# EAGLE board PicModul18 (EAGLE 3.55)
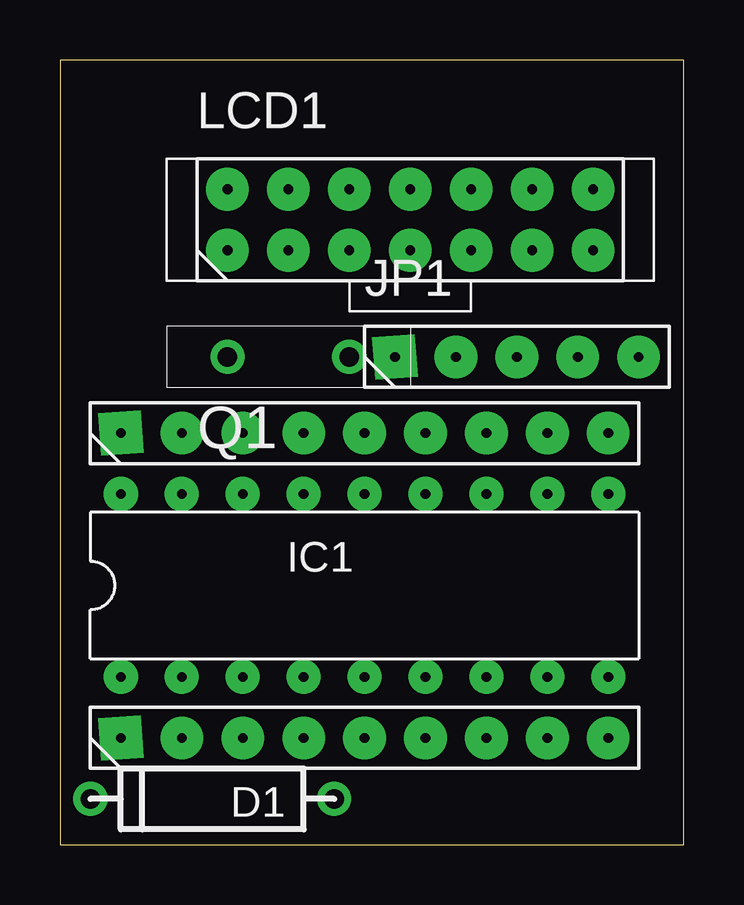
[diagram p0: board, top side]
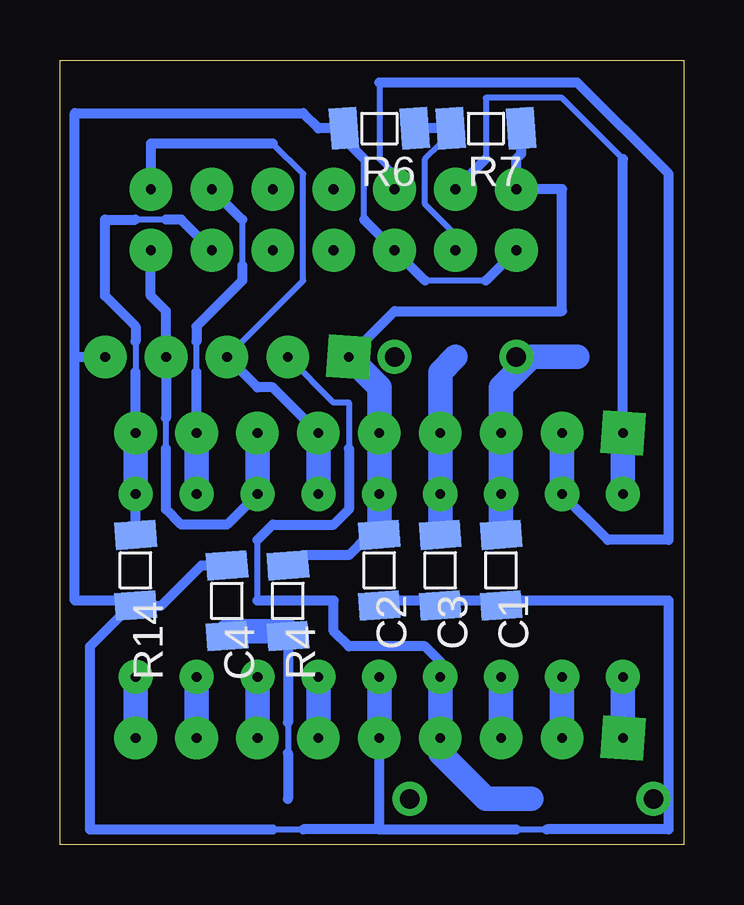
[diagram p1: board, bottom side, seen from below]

Size 26.02 x 32.69 mm. Coordinates in mm from the lower left corner, seen from the top.
Outline: 0,0 26.02,0 26.02,32.69 0,32.69 0,0
Copper layers used: Bottom

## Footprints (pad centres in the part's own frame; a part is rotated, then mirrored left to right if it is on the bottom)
06 = smd 1.143 x 1.702 rotated 4.4:  1.473,0 | smd 1.143 x 1.702 rotated 4.3:  -1.473,0
O04 = drill 0.813 pad 1.422 round:  0,0;  10.16,0
9 = drill 0.406 pad 1.778 square:  0,0 | drill 0.406 pad 1.778 round:  5.08,0;  10.16,0;  12.7,0;  7.62,0;  2.54,0;  15.24,0;  17.78,0;  20.32,0
L-18 = drill 0.406 pad 1.422 round:  -10.16,-3.81;  -7.62,-3.81;  5.08,-3.81;  7.62,-3.81;  -5.08,-3.81;  -2.54,-3.81;  2.54,-3.81;  0,-3.81;  10.16,-3.81;  10.16,3.81;  7.62,3.81;  5.08,3.81;  2.54,3.81;  0,3.81;  -2.54,3.81;  -5.08,3.81;  -7.62,3.81;  -10.16,3.81
5 = drill 0.406 pad 1.778 square:  0,0 | drill 0.406 pad 1.778 round:  5.08,0;  10.16,0;  7.62,0;  2.54,0
7 = drill 0.406 pad 1.778 round:  0,0;  2.54,0;  5.08,0;  7.62,0;  10.16,0;  10.16,2.54;  7.62,2.54;  5.08,2.54;  2.54,2.54;  0,2.54;  12.7,0;  12.7,2.54;  15.24,0;  15.24,2.54
ARZ_ST = drill 0.813 pad 1.422 round:  0,0;  5.08,0

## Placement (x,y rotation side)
C1  27p  [06]  7.62,11.43 90 bottom
C2  100n  [06]  12.7,11.43 90 bottom
C3  27p  [06]  10.16,11.43 90 bottom
C4  100n  [06]  19.05,10.16 90 bottom
D1  BAT41  [O04]  11.43,1.91 180 top
E$1  [9]  2.54,4.45 0 top
E$2  [9]  2.54,17.14 0 top
IC1  16F84P  [L-18]  12.7,10.79 0 top
JP1  PINHD-1X5  [5]  13.97,20.32 0 top
LCD1  LTN211  [7]  6.99,24.77 0 top
Q1  4MHz  [ARZ_ST]  6.99,20.32 0 top
R4  47k  [06]  16.51,10.16 90 bottom
R6  1k  [06]  12.7,29.84 0 bottom
R7  12k  [06]  8.26,29.84 0 bottom
R14  4k7  [06]  22.86,11.43 90 bottom

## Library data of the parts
C1-C4 R4 R6 R7 R14 = mysmd
D1 = holgnorm
E$1 E$2 IC1 LCD1 = holg_plt
JP1 = PINHEAD
Q1 = bts

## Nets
+5V: C2. E$2. IC1. JP1. LCD1. R4. R7.
GND: C1. C2. C3. C4. E$1. IC1. JP1. LCD1. R6. R14.
N$1: C1. E$2. IC1. Q1.
N$3: C3. E$2. IC1. Q1.
N$5: E$2. IC1. LCD1.
N$6: E$2. IC1. LCD1. R14.
N$7: E$2. IC1. JP1. LCD1.
N$8: E$2. IC1. JP1. LCD1.
N$10: C4. D1. R4.
N$12: D1. E$1. IC1. JP1.
N$13: E$2. IC1. LCD1.
N$18: E$2. IC1. LCD1.
N$21: LCD1. R6. R7.
S$1: E$1. IC1.
S$2: E$1. IC1.
S$3: E$1. IC1.
S$4: E$1. IC1.
S$5: E$1. IC1.
S$6: E$1. IC1.
S$7: E$1. IC1.

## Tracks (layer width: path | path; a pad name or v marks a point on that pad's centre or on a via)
+5V
  Bottom 0.254: 16.31,11.63 16.51,11.63
  Bottom 0.406: 6.78,29.84 6.78,28.78 6.99,28.57 6.99,27.3 5.08,27.3 5.08,22.23 12.06,22.23 13.97,20.32 | 12.7,12.9 13.13,12.9 13.97,12.06 15.88,12.06 16.31,11.63
  Bottom 1.016: 13.97,20.32 12.7,19.05 12.7,17.14 12.7,14.61 12.7,12.9
GND
  Bottom 0.254: 8.26,23.5 10.79,23.5 | 13.34,26.04 13.34,28.57 | 8.26,10.16 8.05,9.96 C1. 7.19,9.96 6.99,10.16 | 9.73,9.96 C3. 10.59,9.96 10.79,10.16 | C2. 12.27,9.96 12.06,10.16 | 23.06,9.96 23.29,9.96 23.5,10.16 | 12.7,4.45 12.7,6.99 | 17.14,0.64 15.88,0.64 | 6.99,0.64 5.71,0.64
  Bottom 0.406: 19.05,11.63 20.12,11.63 21.79,9.96 R14. 23.06,9.96 24.77,8.26 24.77,0.64 17.14,0.64 | 12.7,0.64 12.7,4.45 | 6.99,24.77 8.26,23.5 | 10.79,23.5 12.06,24.77 13.34,26.04 | 13.34,28.57 14.17,29.41 R6. 15.24,29.84 15.88,30.48 25.4,30.48 25.4,20.32 | 9.73,9.96 9.53,10.16 8.26,10.16 | 10.79,10.16 12.06,10.16 | 25.4,20.32 25.4,10.16 23.5,10.16 | 25.4,20.32 24.13,20.32 | 6.99,10.16 0.64,10.16 0.64,0.64 5.71,0.64 | 12.7,0.64 15.88,0.64 | 12.7,0.64 6.99,0.64
  Bottom 1.016: 12.7,4.45 12.7,6.99
N$1
  Bottom 1.016: 4.45,20.32 6.35,20.32 7.62,19.05 7.62,17.14 7.62,14.61 7.62,12.9
N$3
  Bottom 1.016: 9.53,20.32 10.16,19.68 10.16,17.14 10.16,14.61 10.16,12.9
N$5
  Bottom 0.254: 20.32,19.68 20.32,20.95 | 18.41,26.04 18.41,24.13
  Bottom 0.406: 18.41,26.04 19.68,27.3 | 20.32,17.14 20.32,19.68 | 18.41,24.13 18.41,23.5 20.32,21.59 20.32,20.95
  Bottom 1.016: 20.32,14.61 20.32,17.14
N$6
  Bottom 0.254: 22.86,20.95 22.86,19.68 | 21.59,26.04 22.86,26.04
  Bottom 0.406: 22.86,12.9 22.86,14.61 | 19.68,24.77 20.95,26.04 21.59,26.04 | E$2. 22.86,19.68 | 22.86,20.95 22.86,21.59 24.13,22.86 24.13,26.04 22.86,26.04
  Bottom 1.016: 22.86,14.61 E$2.
N$7
  Bottom 0.254: 17.78,14.61 17.78,17.14 | 21.59,16.51 21.59,17.78
  Bottom 0.406: 22.23,24.77 22.23,22.86 21.59,22.23 21.59,20.32 21.59,17.78 | 17.78,14.61 19.05,13.34 20.95,13.34 21.59,13.97 21.59,16.51
  Bottom 1.016: 17.78,14.61 17.78,17.14
N$8
  Bottom 0.254: 19.05,20.32 15.88,23.5 15.88,27.94 17.14,29.21
  Bottom 0.406: LCD1. 22.23,29.21 17.14,29.21 | 15.24,17.14 17.14,19.05 17.78,19.05 19.05,20.32
  Bottom 1.016: 15.24,14.61 15.24,17.14
N$10
  Bottom 0.254: 16.51,5.08 16.51,3.81
  Bottom 0.406: R4. 16.51,5.08 | 16.51,3.81 16.51,1.91
  Bottom 1.016: R4. 16.51,8.89 19.05,8.89 C4.
N$12
  Bottom 0.254: JP1. 14.61,18.41 13.97,18.41 13.97,16.51 | 17.78,10.16 17.78,12.7
  Bottom 0.406: 10.16,6.99 10.16,7.62 10.79,8.26 13.97,8.26 14.61,8.89 14.61,10.16 17.78,10.16 | 17.78,12.7 17.14,13.34 14.61,13.34 13.97,13.97 13.97,16.51
  Bottom 1.016: 10.16,6.99 10.16,4.45 10.16,3.81 8.26,1.91 6.35,1.91
N$13
  Bottom 0.254: 8.26,28.57 8.26,31.11 5.08,31.11 2.54,28.57
  Bottom 0.406: 8.26,28.57 9.53,27.3 | 2.54,17.14 2.54,28.57
  Bottom 1.016: IC1. 2.54,17.14
N$18
  Bottom 0.254: 12.06,27.94 12.7,28.57 12.7,31.75
  Bottom 0.406: 12.06,27.94 12.06,27.3 | 12.7,31.75 4.45,31.75 0.64,27.94 0.64,12.7 3.17,12.7 5.08,14.61
  Bottom 1.016: 5.08,14.61 5.08,17.14
N$21
  Bottom 0.254: R7. 10.16,29.84 10.16,29.21 10.79,28.57 10.79,26.67 9.53,25.4
  Bottom 0.406: 10.16,29.84 11.23,29.84 | 9.53,24.77 9.53,25.4
S$1
  Bottom 1.016: E$1. 22.86,6.99
S$2
  Bottom 1.016: 20.32,4.45 20.32,6.99
S$3
  Bottom 1.016: 17.78,4.45 17.78,6.99
S$4
  Bottom 1.016: 15.24,4.45 15.24,6.99
S$5
  Bottom 1.016: 7.62,4.45 7.62,6.99
S$6
  Bottom 1.016: 5.08,4.45 5.08,6.99
S$7
  Bottom 1.016: 2.54,4.45 2.54,6.99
